// Mitsubishi GX Works2 project: 26.灯顺序亮（比较指令）   PLC: FX3U/FX3UC

PROGRAM MAIN
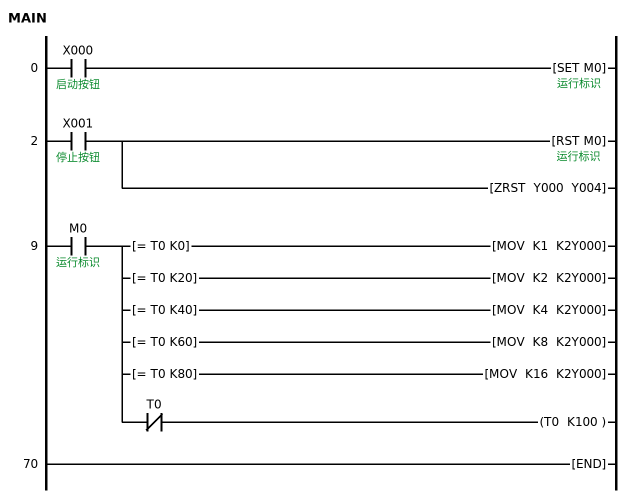
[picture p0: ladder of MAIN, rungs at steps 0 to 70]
0     LD      X000  ; 启动按钮
      SET     M0  ; 运行标识
2     LD      X001  ; 停止按钮
      RST     M0  ; 运行标识
      ZRST    Y000 Y004
9     LD      M0  ; 运行标识
      MPS
      AND=    T0 K0
      MOV     K1 K2Y000
      MRD
      AND=    T0 K20
      MOV     K2 K2Y000
      MRD
      AND=    T0 K40
      MOV     K4 K2Y000
      MRD
      AND=    T0 K60
      MOV     K8 K2Y000
      MRD
      AND=    T0 K80
      MOV     K16 K2Y000
      MPP
      ANI     T0
      OUT     T0 K100
70    END
END_PROGRAM
